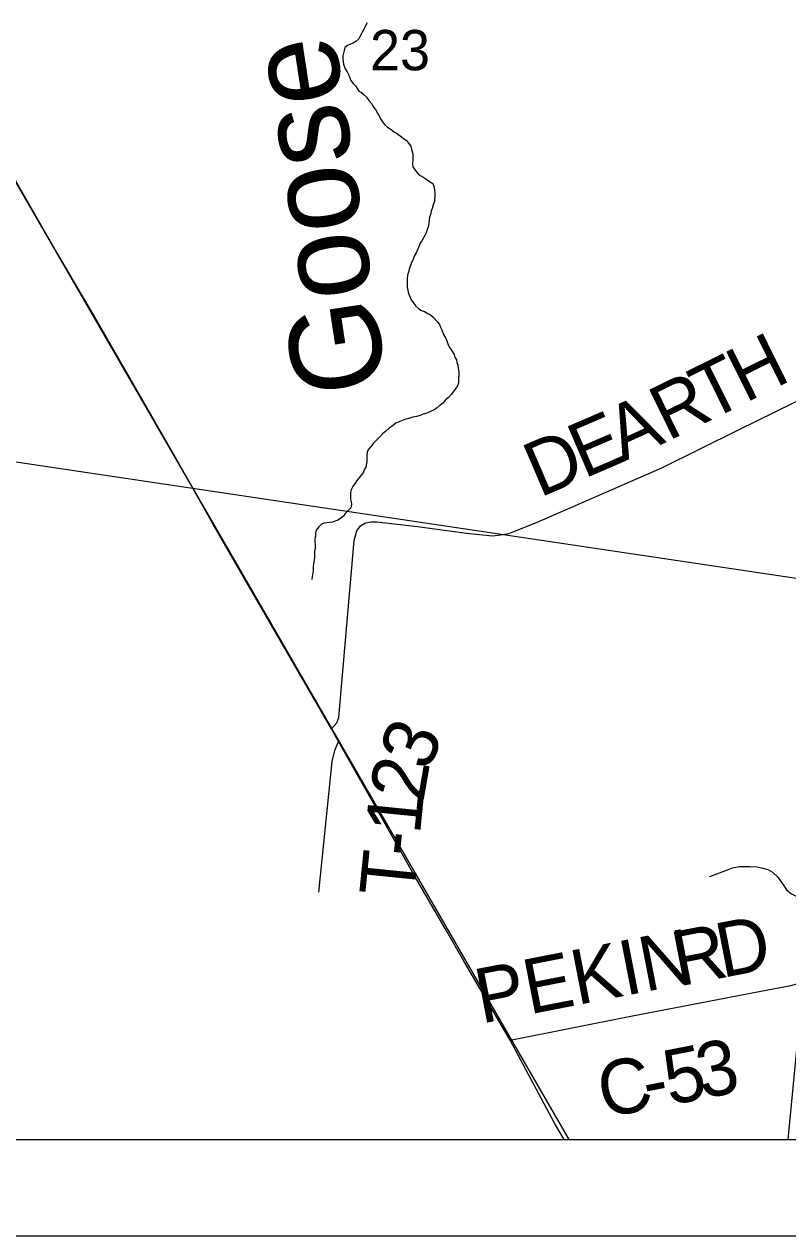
# Model space of a CAD drawing. Extents: x -7.3 to 34, y 0 to 22.
# Drawn here: x 7.551 to 8.344, y 14 to 15.258 of the extents above; entities that cross this region are included whole.
import ezdxf

# ---------------------------------------------------------------- set-up
doc = ezdxf.new("R2010")
doc.units = 0
for name, color, linetype in [('GM_X_Corporation', 7, 'Continuous'), ('GM_X_County_Road', 7, 'Continuous'), ('GM_X_County_Road_Text', 7, 'Continuous'), ('GM_X_Minor_River', 7, 'Continuous'), ('GM_X_Minor_River_Text', 7, 'Continuous'), ('GM_X_Rail_Line', 7, 'Continuous'), ('GM_X_Section_Text', 7, 'Continuous'), ('GM_X_State_Route', 7, 'Continuous'), ('GM_X_Township_Road', 7, 'Continuous'), ('GM_X_Township_Road_Text', 7, 'Continuous'), ('SH_Data', 7, 'Continuous')]:
    doc.layers.add(name, color=color, linetype=linetype)

msp = doc.modelspace()

# ---------------------------------------------------------------- linework, layer by layer
at = {"layer": 'GM_X_Corporation'}
for points in [[(4.3152, 15.5847), (4.2701, 15.1232), (4.2655, 15.0758), (4.2591, 15.0066), (4.246, 14.8644), (4.233, 14.7229), (4.2199, 14.5807), (4.1921, 14.279), (4.1756, 14.1), (8.9, 14.1), (8.9, 19.7858)], [(4.3152, 15.5847), (4.2701, 15.1232), (4.2655, 15.0758), (4.2591, 15.0066), (4.246, 14.8644), (4.233, 14.7229), (4.2199, 14.5807), (4.1921, 14.279), (4.1756, 14.1), (8.3447, 14.1), (8.3604, 14.2653), (8.3676, 14.3403), (8.3685, 14.3492), (8.4214, 14.9056), (8.4562, 15.2161), (8.4601, 15.2687)]]:
    msp.add_lwpolyline(points, dxfattribs=at)
for points in [[(7.4799, 15.8457), (8.4992, 15.7029), (8.4066, 14.6743), (7.3939, 14.8252)], [(7.3299, 14.1), (8.355, 14.1), (8.4066, 14.6743), (7.3939, 14.8252), (7.354, 14.3269)]]:
    msp.add_lwpolyline(points, close=True, dxfattribs=at)
at = {"layer": 'GM_X_County_Road'}
for points in [[(7.8704, 14.526), (7.876, 14.5324), (7.8781, 14.5381), (7.8939, 14.7215), (7.8968, 14.7318), (7.9004, 14.737), (7.9057, 14.74), (7.9114, 14.7411), (7.9173, 14.7411), (7.9598, 14.7363), (8.0106, 14.7293), (8.0376, 14.7266), (8.0458, 14.7274), (8.0546, 14.7289), (8.0834, 14.7403), (8.2135, 14.7969), (8.293, 14.8366), (8.4073, 14.8926), (8.4169, 14.9004), (8.4216, 14.9051), (8.4272, 14.9163), (8.4292, 14.9335), (8.4564, 15.2156)], [(8.0558, 14.2031), (8.1811, 14.2279), (8.3163, 14.254), (8.3475, 14.2599), (8.3559, 14.2622), (8.3606, 14.2648), (8.3644, 14.267), (8.3683, 14.2726), (8.3687, 14.2737)]]:
    msp.add_lwpolyline(points, dxfattribs=at)
at = {"layer": 'GM_X_Minor_River'}
for points in [[(7.9073, 15.2588), (7.9049, 15.2543), (7.9037, 15.2517), (7.9022, 15.2491), (7.9006, 15.2457), (7.8986, 15.2423), (7.8955, 15.2397), (7.8928, 15.2379), (7.8901, 15.2368)], [(7.8901, 15.2368), (7.8871, 15.2353), (7.8844, 15.2335), (7.8835, 15.2301), (7.8827, 15.2275), (7.8823, 15.2248), (7.8822, 15.2214), (7.8829, 15.2161), (7.8846, 15.2111), (7.8865, 15.208), (7.8883, 15.2045), (7.8905, 15.1992), (7.893, 15.1961), (7.8953, 15.1934), (7.8971, 15.1907), (7.8989, 15.188), (7.9016, 15.1868), (7.9042, 15.1841), (7.9068, 15.1817), (7.909, 15.1783), (7.9119, 15.1752), (7.9141, 15.1713), (7.9163, 15.1686), (7.9178, 15.1655), (7.92, 15.1624), (7.9211, 15.1594), (7.9233, 15.1563), (7.9255, 15.1536), (7.9285, 15.1505), (7.9322, 15.1481), (7.9359, 15.1454), (7.9386, 15.1442), (7.9416, 15.1418), (7.9449, 15.1391), (7.9483, 15.1368), (7.9505, 15.1341), (7.9527, 15.131), (7.9537, 15.126), (7.9548, 15.1229), (7.9547, 15.1203), (7.9547, 15.1165), (7.9546, 15.1131), (7.9549, 15.1096), (7.9571, 15.1062), (7.96, 15.1027), (7.9626, 15.1004), (7.9653, 15.0992), (7.9683, 15.0972), (7.9712, 15.0949), (7.9757, 15.0921), (7.9768, 15.0894), (7.9775, 15.086), (7.9778, 15.0818), (7.9777, 15.0791), (7.9773, 15.0761), (7.9772, 15.0734), (7.976, 15.0701), (7.9748, 15.0663), (7.974, 15.0636), (7.9731, 15.0599), (7.9723, 15.0572), (7.9719, 15.0542), (7.9714, 15.0512), (7.971, 15.0481), (7.9698, 15.0444), (7.9686, 15.041), (7.9674, 15.0383), (7.9658, 15.0357), (7.9642, 15.0327), (7.9626, 15.0301), (7.9606, 15.0259), (7.9586, 15.021), (7.9563, 15.0169), (7.9551, 15.0135), (7.9531, 15.009), (7.951, 15.0034), (7.9502, 15.0003), (7.9494, 14.9969), (7.9489, 14.9931), (7.9488, 14.9882), (7.9491, 14.9848), (7.9498, 14.9813), (7.9505, 14.9779), (7.9516, 14.9748), (7.9526, 14.9722), (7.9549, 14.9691), (7.9578, 14.9648), (7.9611, 14.9621), (7.9638, 14.9605), (7.9668, 14.9593), (7.9705, 14.9573), (7.9731, 14.9558), (7.9758, 14.9534), (7.9802, 14.9488), (7.9824, 14.9457), (7.9835, 14.943), (7.9849, 14.9403), (7.9867, 14.9353), (7.9886, 14.9319), (7.99, 14.9288), (7.9911, 14.9257)], [(7.9911, 14.9257), (7.9929, 14.9219), (7.9951, 14.9192), (7.9977, 14.9146), (7.9984, 14.9119), (8.0002, 14.9092), (8.0005, 14.9065), (8.0016, 14.9039), (8.0019, 14.9004), (8.0026, 14.8966), (8.0025, 14.894), (8.0024, 14.8894), (8.0023, 14.8852), (8.0011, 14.8822), (7.9996, 14.8796), (7.9972, 14.8762), (7.9945, 14.8732), (7.9918, 14.8699), (7.9891, 14.868), (7.9859, 14.8643), (7.9832, 14.8621), (7.9802, 14.8595), (7.9771, 14.8573), (7.9732, 14.8555), (7.9694, 14.8537), (7.9656, 14.8526), (7.9625, 14.8515), (7.9587, 14.8505), (7.9549, 14.8498), (7.9507, 14.8484), (7.9465, 14.8473), (7.9412, 14.8451), (7.9373, 14.8433), (7.9335, 14.8404), (7.9304, 14.8382), (7.9269, 14.8352), (7.9234, 14.8322), (7.9203, 14.8289), (7.9172, 14.8259), (7.9141, 14.8226), (7.9114, 14.8196), (7.9083, 14.8158), (7.9075, 14.8132), (7.907, 14.8102), (7.9069, 14.8068), (7.9069, 14.8041), (7.9068, 14.8014), (7.906, 14.7977), (7.9044, 14.795), (7.9036, 14.7924), (7.9013, 14.7894), (7.8989, 14.7864), (7.8966, 14.7838), (7.895, 14.7812), (7.8927, 14.7778), (7.8907, 14.7744), (7.8902, 14.7714), (7.8902, 14.7688), (7.8901, 14.7646), (7.8908, 14.7619), (7.8911, 14.7589), (7.8903, 14.7555), (7.8876, 14.7529), (7.8845, 14.7495), (7.8829, 14.7469), (7.8802, 14.7447), (7.8767, 14.7425), (7.874, 14.7417), (7.8714, 14.7407), (7.8687, 14.7403), (7.866, 14.74), (7.8626, 14.7397), (7.8599, 14.7386), (7.8572, 14.7357), (7.8545, 14.7323), (7.8537, 14.7293), (7.8536, 14.7262), (7.8532, 14.7236), (7.8531, 14.7206), (7.8534, 14.7171), (7.8533, 14.7137), (7.8529, 14.7107), (7.8528, 14.7069), (7.8527, 14.7042), (7.8523, 14.7012), (7.8518, 14.6978), (7.8514, 14.6944), (7.8513, 14.691), (7.8509, 14.6875), (7.8504, 14.6845), (7.85, 14.6811)]]:
    msp.add_lwpolyline(points, dxfattribs=at)
at = {"layer": 'GM_X_Rail_Line'}
msp.add_lwpolyline([(8.1171, 14.1), (7.77, 14.7008), (7.4272, 15.293), (6.5394, 16.8246), (6.3886, 17.0851), (6.2996, 17.2555), (6.2775, 17.3138), (6.2567, 17.3864), (6.213, 17.5514), (6.1948, 17.6035), (6.1703, 17.6358), (6.1218, 17.6697), (5.9568, 17.7678)], dxfattribs=at)
at = {"layer": 'GM_X_State_Route'}
for points in [[(8.0558, 14.2031), (8.0084, 14.2839), (7.9897, 14.3165), (7.9577, 14.3718), (7.9127, 14.4514), (7.8775, 14.5131), (7.8704, 14.526), (7.7981, 14.651), (7.748, 14.7378), (7.707, 14.8101), (7.664, 14.8848), (7.6231, 14.9559), (7.5815, 15.0273), (7.5477, 15.0857), (7.4974, 15.1731), (7.4652, 15.2288), (7.4344, 15.2802)], [(8.112, 14.1), (8.1021, 14.1168), (8.0558, 14.2031)]]:
    msp.add_lwpolyline(points, dxfattribs=at)
at = {"layer": 'GM_X_Township_Road'}
for points in [[(7.8571, 14.3565), (7.871, 14.4924), (7.8737, 14.5038), (7.8775, 14.5131)], [(8.2633, 14.3728), (8.2816, 14.3797), (8.2868, 14.3818), (8.2941, 14.3833), (8.3046, 14.3833), (8.3124, 14.3828), (8.3181, 14.3816), (8.3234, 14.3802), (8.3283, 14.3774), (8.3338, 14.3721), (8.3396, 14.3638), (8.343, 14.359), (8.3481, 14.3549), (8.3536, 14.3521), (8.3618, 14.3493), (8.3687, 14.3487), (8.3729, 14.3481), (8.3767, 14.3463), (8.3799, 14.3435)]]:
    msp.add_lwpolyline(points, dxfattribs=at)
at = {"layer": 'SH_Data'}
for p, q in [((2.1, 14.1), (8.9, 14.1)), ((2, 14), (9, 14))]:
    msp.add_line(p, q, dxfattribs=at)

# ---------------------------------------------------------------- texts
at = {"layer": 'GM_X_County_Road_Text'}
for s, height, rotation, p in [('H', 0.0568, 26.4311, (8.3, 14.864)), ('T', 0.0568, 26.4286, (8.262, 14.8451)), ('R', 0.0568, 26.1253, (8.2198, 14.8244)), ('A', 0.0568, 24.4943, (8.1727, 14.8029)), ('E', 0.0568, 23.328, (8.1325, 14.7855)), ('D', 0.0568, 23.2431, (8.0865, 14.7658)), ('D', 0.0568, 11.0286, (8.2759, 14.2675)), ('PEKIN', 0.05682, 11.0127, (8.0259, 14.22)), ('R', 0.0568, 11.0128, (8.2305, 14.2586)), ('5', 0.0568, 11.0152, (8.2212, 14.1353)), ('3', 0.0568, 11.0353, (8.2553, 14.142)), ('C', 0.0568, 11.0127, (8.153, 14.122)), ('-', 0.0568, 11.0129, (8.1985, 14.1309))]:
    msp.add_text(s, height=height, rotation=rotation, dxfattribs=at).set_placement(p)
at = {"layer": 'GM_X_Minor_River_Text'}
msp.add_text('Goose', height=0.09468, rotation=98.6235, dxfattribs=at).set_placement((7.9287, 14.8806))
at = {"layer": 'GM_X_Section_Text'}
msp.add_text('23', height=0.04186, rotation=0, dxfattribs=at).set_placement((7.9104, 15.2097))
at = {"layer": 'GM_X_Township_Road_Text'}
for s, rotation, p in [('3', 67.5482, (7.9707, 14.4808)), ('2', 80.0843, (7.9656, 14.4494)), ('1', 84.2767, (7.9622, 14.4157)), ('-', 84.2451, (7.9599, 14.3925)), ('T', 84.2561, (7.9557, 14.3502))]:
    msp.add_text(s, height=0.0568, rotation=rotation, dxfattribs=at).set_placement(p)

doc.saveas('drawing.dxf')
